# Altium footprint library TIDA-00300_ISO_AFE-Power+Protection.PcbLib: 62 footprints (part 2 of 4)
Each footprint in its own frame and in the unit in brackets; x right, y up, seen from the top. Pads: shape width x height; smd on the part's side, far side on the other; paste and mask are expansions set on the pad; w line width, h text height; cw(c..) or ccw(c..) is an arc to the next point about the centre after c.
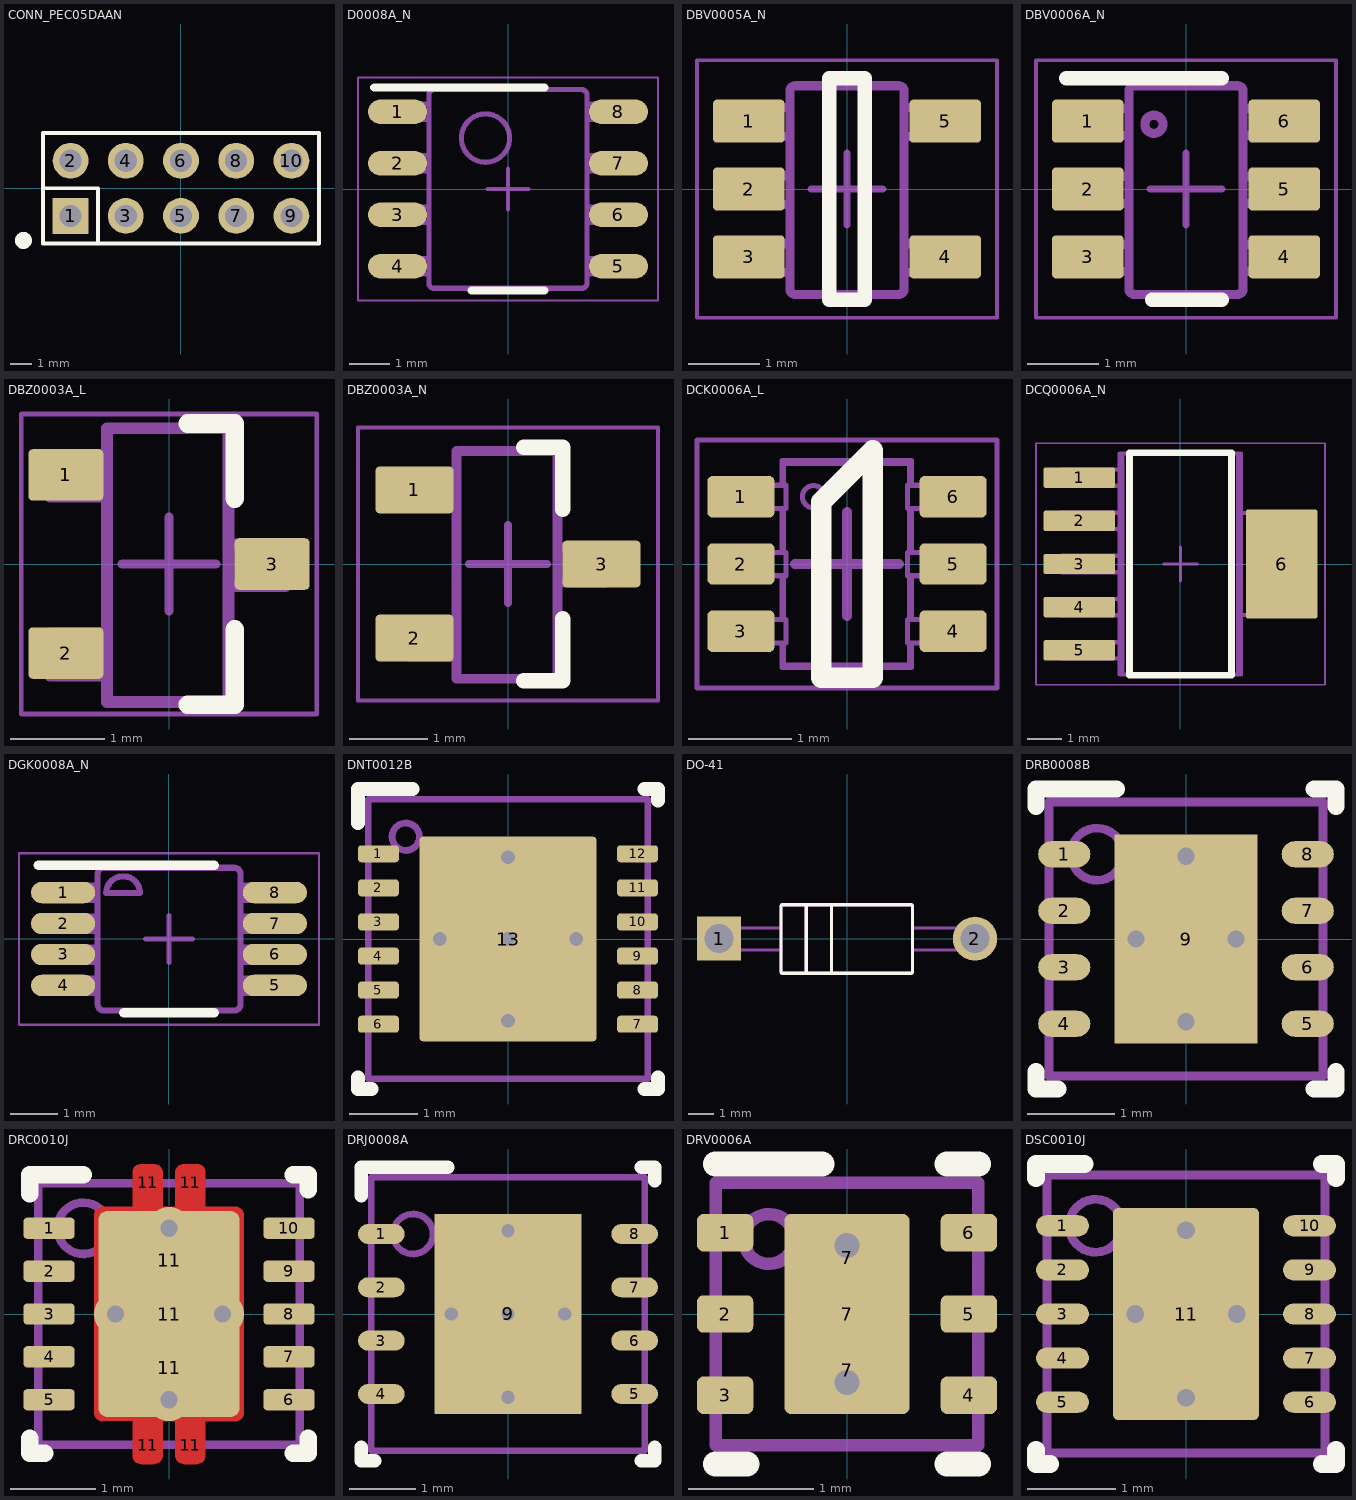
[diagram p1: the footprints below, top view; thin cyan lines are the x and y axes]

## CONN_PEC05DAAN [mm] "SULLINS"
height 8.382
pads (10):
  rect 1.65x1.65 hole 1.016 mask+0: 1(-5.08,-1.27)
  round 1.65 hole 1.016 mask+0: 2(-5.08,1.27) 3(-2.54,-1.27) 4(-2.54,1.27) 5(0,-1.27) 6(0,1.27) 7(2.54,-1.27) 8(2.54,1.27) 9(5.08,-1.27) 10(5.08,1.27)
Top Overlay:
  circle w0.381: c-7.25,-2.4 r0.203
  lines w0.178: -6.35,0 -3.81,0 -3.81,-2.54 ; -6.35,-2.54 -6.35,2.54 6.35,2.54 6.35,-2.54 -6.35,-2.54
Mechanical 5:
  rectangle: -5.588,-1.778 -4.572,-0.762
  lines w0.076: -6.35,-2.54 -6.35,2.54 6.35,2.54 6.35,-2.54 -6.35,-2.54
  lines w0.127: -6.35,-2.54 6.35,-2.54 6.35,2.54 -6.35,2.54 -6.35,-2.54
  text ".Designator" at -0.225,-0.532 h0.51
3D body: height 2.54, standoff 0, extent -6.349,-2.539 6.349,2.539
3D body: height 8.38, standoff -3.05, extent 4.763,0.953 5.398,1.588
3D body: height 8.38, standoff -3.05, extent 4.763,-1.587 5.398,-0.952
3D body: height 8.38, standoff -3.05, extent 2.223,0.953 2.858,1.588
3D body: height 8.38, standoff -3.05, extent 2.223,-1.587 2.858,-0.952
3D body: height 8.38, standoff -3.05, extent -0.317,0.953 0.318,1.588
3D body: height 8.38, standoff -3.05, extent -0.317,-1.587 0.318,-0.952
3D body: height 8.38, standoff -3.05, extent -2.857,-1.587 -2.222,-0.952
3D body: height 8.38, standoff -3.05, extent -2.857,0.953 -2.222,1.588
3D body: height 8.38, standoff -3.05, extent -5.397,0.953 -4.762,1.588
3D body: height 8.38, standoff -3.05, extent -5.397,-1.587 -4.762,-0.952

## D0008A_N [mm] "SOIC, 8-Leads, Body 4.9x3.9mm, Pitch 1.27mm, IPC Medium Density"
height 1.75
pads (8):
  oval 1.45x0.6 smd: 1(-2.725,1.905) 2(-2.725,0.635) 3(-2.725,-0.635) 4(-2.725,-1.905) 5(2.725,-1.905) 6(2.725,-0.635) 7(2.725,0.635) 8(2.725,1.905)
Top Overlay:
  lines w0.2: -3.3,2.5 0.9,2.5 ; -0.9,-2.5 0.9,-2.5
Mechanical 5:
  lines w0.127: -2.375,-2.095 -1.995,-2.095 -1.952,-2.095 -1.952,-1.715 -1.995,-1.715 -2.375,-1.715 ; -2.375,-2.095 -2.589,-2.095 -3.002,-2.095 -3.002,-1.715 -2.589,-1.715 -2.375,-1.715 ; -2.375,-2.095 -2.375,-1.715 ; -2.375,-0.825 -1.995,-0.825 -1.952,-0.825 -1.952,-0.445 -1.995,-0.445 -2.375,-0.445 ; -2.375,-0.825 -2.589,-0.825 -3.002,-0.825 -3.002,-0.445 -2.589,-0.445 -2.375,-0.445 ; -2.375,-0.825 -2.375,-0.445 ; -2.375,0.445 -1.995,0.445 -1.952,0.445 -1.952,0.825 -1.995,0.825 -2.375,0.825 ; -2.375,0.445 -2.589,0.445 -3.002,0.445 -3.002,0.825 -2.589,0.825 -2.375,0.825 ; -2.375,0.445 -2.375,0.825 ; -2.375,1.715 -1.995,1.715 -1.952,1.715 -1.952,2.095 -1.995,2.095 -2.375,2.095 ; -2.375,1.715 -2.589,1.715 -3.002,1.715 -3.002,2.095 -2.589,2.095 -2.375,2.095 ; -2.375,1.715 -2.375,2.095 ; -0.332,-2.45 -1.825,-2.45 -1.826,-2.45 cw(c-1.825,-2.323) -1.952,-2.324 -1.952,-2.323 -1.952,2.323 -1.952,2.324 cw(c-1.825,2.323) -1.826,2.45 -1.825,2.45 -0.332,2.45 ; -0.332,-2.45 -0.182,-2.45 ; -0.332,-2.45 -0.182,-2.45 ; -0.332,2.45 -0.182,2.45 ; -0.332,2.45 -0.182,2.45 ; -0.182,-2.45 0.178,-2.45 ; -0.182,2.45 0.178,2.45 ; 0.178,-2.45 0.328,-2.45 ; 0.178,-2.45 0.328,-2.45 ; 0.178,2.45 0.328,2.45 ; 0.178,2.45 0.328,2.45 ; 0.328,-2.45 1.821,-2.45 1.822,-2.45 ccw(c1.821,-2.323) 1.948,-2.324 1.948,-2.323 1.948,2.323 1.948,2.324 ccw(c1.821,2.323) 1.822,2.45 1.821,2.45 0.328,2.45 ; 2.371,-2.095 2.585,-2.095 2.998,-2.095 2.998,-1.715 2.585,-1.715 2.371,-1.715 ; 2.371,-2.095 1.991,-2.095 1.948,-2.095 1.948,-1.715 1.991,-1.715 2.371,-1.715 ; 2.371,-2.095 2.371,-1.715 ; 2.371,-0.825 2.585,-0.825 2.998,-0.825 2.998,-0.445 2.585,-0.445 2.371,-0.445 ; 2.371,-0.825 1.991,-0.825 1.948,-0.825 1.948,-0.445 1.991,-0.445 2.371,-0.445 ; 2.371,-0.825 2.371,-0.445 ; 2.371,0.445 2.585,0.445 2.998,0.445 2.998,0.825 2.585,0.825 2.371,0.825 ; 2.371,0.445 1.991,0.445 1.948,0.445 1.948,0.825 1.991,0.825 2.371,0.825 ; 2.371,0.445 2.371,0.825 ; 2.371,1.715 2.585,1.715 2.998,1.715 2.998,2.095 2.585,2.095 2.371,2.095 ; 2.371,1.715 1.991,1.715 1.948,1.715 1.948,2.095 1.991,2.095 2.371,2.095 ; 2.371,1.715 2.371,2.095 ; -0.555,0.659 cw(c-0.555,1.256) -0.555,1.853 cw(c-0.555,1.256) -0.555,0.659
  text ".Designator" at 0.605,-0.197 h0.51
Mechanical 15:
  lines w0.05: -3.7,-2.75 3.7,-2.75 3.7,2.75 -3.7,2.75 -3.7,-2.75
  lines w0.1: -0.5,0 0.5,0 ; 0,-0.5 0,0.5
3D body "D0008A.stp": height 1.63, standoff 0, extent -3,-2.45 3,2.45

## DBV0005A_N [mm] "SOT23, 5-Leads, Body 2.9x1.6mm, Pitch 0.95mm, Lead Span 2.8mm, IPC Medium Density"
height 1.45
pads (5):
  rrect17% 1x0.6 smd: 1(-1.375,0.95) 2(-1.375,0) 3(-1.375,-0.95) 4(1.375,-0.95) 5(1.375,0.95)
Top Overlay:
  lines w0.2: -0.25,-1.55 -0.25,1.55 0.25,1.55 0.25,-1.55 -0.25,-1.55
Mechanical 5:
  lines w0.127: -0.801,1.371 cw(c-0.725,1.37) -0.725,1.446 ; -0.801,1.37 -0.801,1.371 ; -0.801,1.37 -0.801,-1.399 -0.801,-1.4 ccw(c-0.725,-1.399) -0.725,-1.475 ; -0.725,-1.475 0.723,-1.475 0.724,-1.475 ccw(c0.723,-1.399) 0.799,-1.4 0.799,-1.399 0.799,1.37 ; -0.725,-1.475 -0.725,-1.475 ; -0.725,1.446 -0.725,1.446 ; -0.725,1.446 0.723,1.446 0.724,1.446 cw(c0.723,1.37) 0.799,1.371 ; 0.799,1.37 0.799,1.371 ; -1.423,-1.167 -1.423,-0.767 -1.199,-0.767 -1.105,-0.767 -1.088,-0.767 -0.835,-0.767 -0.801,-0.767 -0.801,-1.167 -0.835,-1.167 -1.088,-1.167 -1.105,-1.167 -1.199,-1.167 -1.423,-1.167 ; -1.423,-0.215 -1.423,0.186 -1.199,0.186 -1.105,0.186 -1.088,0.186 -0.835,0.186 -0.801,0.186 -0.801,-0.215 -0.835,-0.215 -1.088,-0.215 -1.105,-0.215 -1.199,-0.215 -1.423,-0.215 ; -1.423,0.738 -1.423,1.138 -1.199,1.138 -1.105,1.138 -1.088,1.138 -0.835,1.138 -0.801,1.138 -0.801,0.738 -0.835,0.738 -1.088,0.738 -1.105,0.738 -1.199,0.738 -1.423,0.738 ; 0.799,-1.167 0.834,-1.167 1.087,-1.167 1.103,-1.167 1.198,-1.167 1.422,-1.167 1.422,-0.767 1.198,-0.767 1.103,-0.767 1.087,-0.767 0.834,-0.767 0.799,-0.767 0.799,-1.167 ; 0.799,0.738 0.834,0.738 1.087,0.738 1.103,0.738 1.198,0.738 1.422,0.738 1.422,1.138 1.198,1.138 1.103,1.138 1.087,1.138 0.834,1.138 0.799,1.138 0.799,0.738
  text ".Designator" at 0.25,-1.081 h0.51
Mechanical 15:
  lines w0.05: -2.1,-1.8 -2.1,1.8 2.1,1.8 2.1,-1.8 -2.1,-1.8
  lines w0.1: -0.5,0 0.5,0 ; 0,-0.5 0,0.5
3D body "DBV0005A.stp": height 1.09, standoff 0, extent -1.422,-1.461 1.423,1.46

## DBV0006A_N [mm] "SOT23, 6-Leads, Body 2.9x1.6mm, Pitch 0.95mm, Lead Span 2.8mm, IPC Medium Density"
height 1.45
pads (6):
  rrect17% 1x0.6 smd: 1(-1.375,0.95) 2(-1.375,0) 3(-1.375,-0.95) 4(1.375,-0.95) 5(1.375,0) 6(1.375,0.95)
Top Overlay:
  lines w0.2: -1.675,1.55 0.5,1.55 ; -0.475,-1.55 0.5,-1.55
Mechanical 5:
  lines w0.127: 0.724,-1.475 ccw(c0.723,-1.399) 0.8,-1.399 0.8,1.37 ccw(c0.723,1.37) 0.724,1.446 ; 0.723,-1.475 -0.724,-1.475 -0.725,-1.475 cw(c-0.724,-1.399) -0.801,-1.399 -0.801,1.37 cw(c-0.724,1.37) -0.725,1.446 -0.724,1.446 0.723,1.446 ; 0.723,-1.475 0.724,-1.475 ; 0.723,1.446 0.724,1.446 ; -1.423,-1.154 -1.423,-0.78 -1.206,-0.78 -1.113,-0.78 -1.081,-0.78 -0.828,-0.78 -0.801,-0.78 -0.801,-1.154 -0.828,-1.154 -1.081,-1.154 -1.113,-1.154 -1.206,-1.154 -1.423,-1.154 ; -1.423,-0.202 -1.423,0.173 -1.206,0.173 -1.113,0.173 -1.081,0.173 -0.828,0.173 -0.801,0.173 -0.801,-0.202 -0.828,-0.202 -1.081,-0.202 -1.113,-0.202 -1.206,-0.202 -1.423,-0.202 ; -1.423,0.751 -1.423,1.125 -1.206,1.125 -1.113,1.125 -1.081,1.125 -0.828,1.125 -0.801,1.125 -0.801,0.751 -0.828,0.751 -1.081,0.751 -1.113,0.751 -1.206,0.751 -1.423,0.751 ; -0.577,0.906 ccw(c-0.45,0.906) -0.323,0.906 ccw(c-0.45,0.906) -0.577,0.906 ; 0.8,-1.154 0.8,-0.78 0.827,-0.78 1.08,-0.78 1.112,-0.78 1.205,-0.78 1.422,-0.78 1.422,-1.154 1.205,-1.154 1.112,-1.154 1.08,-1.154 0.827,-1.154 0.8,-1.154 ; 0.8,-0.202 0.8,0.173 0.827,0.173 1.08,0.173 1.112,0.173 1.205,0.173 1.422,0.173 1.422,-0.202 1.205,-0.202 1.112,-0.202 1.08,-0.202 0.827,-0.202 0.8,-0.202 ; 0.8,0.751 0.8,1.125 0.827,1.125 1.08,1.125 1.112,1.125 1.205,1.125 1.422,1.125 1.422,0.751 1.205,0.751 1.112,0.751 1.08,0.751 0.827,0.751 0.8,0.751
  text ".Designator" at -0.207,0.323 h0.51
Mechanical 15:
  lines w0.05: -2.1,-1.8 -2.1,1.8 2.1,1.8 2.1,-1.8 -2.1,-1.8
  lines w0.1: -0.5,0 0.5,0 ; 0,-0.5 0,0.5
3D body "DBV0006A.stp": height 1.12, standoff 0, extent -1.422,-1.461 1.423,1.46

## DBZ0003A_L [mm] "SOT23, 3-Leads, Body 2.9x1.3mm, Pitch 0.95mm, Lead Span 2.4mm, IPC High Density"
height 1.12
pads (3):
  rrect18% 0.8x0.55 smd: 1(-1.1,0.95) 2(-1.1,-0.95) 3(1.1,0)
Top Overlay:
  lines w0.2: 0.2,-1.5 0.7,-1.5 0.7,-0.7 ; 0.2,1.5 0.7,1.5 0.7,0.7
Mechanical 5:
  lines w0.127: -1.27,-1.187 -1.063,-1.187 -1.005,-1.187 -0.814,-1.187 -0.66,-1.187 -0.66,-0.743 -0.814,-0.743 -1.005,-0.743 -1.063,-0.743 -1.27,-0.743 -1.27,-1.187 ; -1.27,0.718 -1.063,0.718 -1.005,0.718 -0.814,0.718 -0.66,0.718 -0.66,1.162 -0.814,1.162 -1.005,1.162 -1.063,1.162 -1.27,1.162 -1.27,0.718 ; -0.66,-1.473 0.635,-1.473 0.635,1.448 -0.66,1.448 -0.66,-1.473 ; 0.635,-0.235 0.635,0.21 0.789,0.21 0.98,0.21 1.037,0.21 1.245,0.21 1.245,-0.235 1.037,-0.235 0.98,-0.235 0.789,-0.235 0.635,-0.235
  text ".Designator" at 0.186,-1.108 h0.51
Mechanical 15:
  lines w0.05: -1.575,-1.6 1.575,-1.6 1.575,1.6 -1.575,1.6 -1.575,-1.6
  lines w0.1: -0.5,0 0.5,0 ; 0,-0.5 0,0.5
3D body "DBZ0003A.stp": height 0.98, standoff 0, extent -1.257,-1.461 1.258,1.461

## DBZ0003A_N [mm] "SOT23, 3-Leads, Body 2.9x1.3mm, Pitch 0.95mm, Lead Span 2.4mm, IPC Medium Density"
height 1.12
pads (3):
  rrect17% 1x0.6 smd: 1(-1.2,0.95) 2(-1.2,-0.95) 3(1.2,0)
Top Overlay:
  lines w0.2: 0.2,-1.5 0.7,-1.5 0.7,-0.7 ; 0.2,1.5 0.7,1.5 0.7,0.7
Mechanical 5:
  lines w0.127: -1.27,-1.187 -1.27,-0.743 -1.063,-0.743 -1.005,-0.743 -0.814,-0.743 -0.66,-0.743 -0.66,-1.187 -0.814,-1.187 -1.005,-1.187 -1.063,-1.187 -1.27,-1.187 ; -1.27,0.718 -1.27,1.162 -1.063,1.162 -1.005,1.162 -0.814,1.162 -0.66,1.162 -0.66,0.718 -0.814,0.718 -1.005,0.718 -1.063,0.718 -1.27,0.718 ; -0.66,-1.473 -0.66,1.448 0.635,1.448 0.635,-1.473 -0.66,-1.473 ; 0.635,-0.235 0.789,-0.235 0.98,-0.235 1.037,-0.235 1.245,-0.235 1.245,0.21 1.037,0.21 0.98,0.21 0.789,0.21 0.635,0.21 0.635,-0.235
  text ".Designator" at -0.203,0.051 h0.51
Mechanical 15:
  lines w0.05: -1.925,-1.75 1.925,-1.75 1.925,1.75 -1.925,1.75 -1.925,-1.75
  lines w0.1: -0.5,0 0.5,0 ; 0,-0.5 0,0.5
3D body "DBZ0003A.stp": height 0.98, standoff 0, extent -1.257,-1.461 1.258,1.461

## DCK0006A_L [mm] "SOT23, 6-Leads, Body 2x1.3mm, Pitch 0.65mm, Lead Span 2.1mm, IPC High Density"
height 1.1
pads (6):
  rrect25% 0.65x0.4 smd: 1(-1.025,0.65) 2(-1.025,0) 3(-1.025,-0.65) 4(1.025,-0.65) 5(1.025,0) 6(1.025,0.65)
Top Overlay:
  lines w0.2: -0.25,-1.1 -0.25,0.6 0.25,1.1 0.25,-1.1 -0.25,-1.1
Mechanical 5:
  lines w0.05: -0.613,-0.763 -0.613,-0.976 0.607,-0.976 0.607,-0.763 ; -0.613,-0.538 -0.613,-0.113 ; -0.613,0.112 -0.613,0.537 ; -0.613,0.762 -0.613,0.974 0.607,0.974 0.607,0.762 ; 0.607,-0.538 0.607,-0.113 ; 0.607,0.112 0.607,0.537 ; -0.628,-0.763 -0.628,-1.001 0.622,-1.001 0.622,-0.763 ; -0.628,-0.763 -0.853,-0.763 -0.865,-0.763 -0.959,-0.763 -1.143,-0.763 -1.143,-0.538 -0.959,-0.538 -0.865,-0.538 -0.853,-0.538 -0.628,-0.538 ; -0.628,-0.763 -0.591,-0.763 -0.591,-0.538 -0.628,-0.538 ; -0.628,-0.538 -0.628,-0.113 ; -0.628,-0.113 -0.853,-0.113 -0.865,-0.113 -0.959,-0.113 -1.143,-0.113 -1.143,0.112 -0.959,0.112 -0.865,0.112 -0.853,0.112 -0.628,0.112 ; -0.628,-0.113 -0.591,-0.113 -0.591,0.112 -0.628,0.112 ; -0.628,0.112 -0.628,0.537 ; -0.628,0.537 -0.853,0.537 -0.865,0.537 -0.959,0.537 -1.143,0.537 -1.143,0.762 -0.959,0.762 -0.865,0.762 -0.853,0.762 -0.628,0.762 ; -0.628,0.537 -0.591,0.537 -0.591,0.762 -0.628,0.762 ; -0.628,0.762 -0.628,0.999 0.622,0.999 0.622,0.762 ; 0.622,-0.763 0.847,-0.763 0.859,-0.763 0.953,-0.763 1.137,-0.763 1.137,-0.538 0.953,-0.538 0.859,-0.538 0.847,-0.538 0.622,-0.538 ; 0.622,-0.763 0.585,-0.763 0.585,-0.538 0.622,-0.538 ; 0.622,-0.538 0.622,-0.113 ; 0.622,-0.113 0.585,-0.113 0.585,0.112 0.622,0.112 ; 0.622,-0.113 0.847,-0.113 0.859,-0.113 0.953,-0.113 1.137,-0.113 1.137,0.112 0.953,0.112 0.859,0.112 0.847,0.112 0.622,0.112 ; 0.622,0.112 0.622,0.537 ; 0.622,0.537 0.847,0.537 0.859,0.537 0.953,0.537 1.137,0.537 1.137,0.762 0.953,0.762 0.859,0.762 0.847,0.762 0.622,0.762 ; 0.622,0.537 0.585,0.537 0.585,0.762 0.622,0.762 ; -0.432,0.65 cw(c-0.323,0.65) -0.215,0.65 cw(c-0.323,0.65) -0.432,0.65
  text ".Designator" at -0.051,0.66 h0.51
Mechanical 15:
  lines w0.05: -1.45,-1.2 1.45,-1.2 1.45,1.2 -1.45,1.2 -1.45,-1.2
  lines w0.1: -0.5,0 0.5,0 ; 0,-0.5 0,0.5
3D body "DCK0006A.stp": height 0.95, standoff 0, extent -1.14,-1 1.14,1

## DCQ0006A_N [mm] "SOT223, 6-Leads, Body 6.6x7.3mm (max), Pitch 1.27mm, IPC Medium Density"
height 1.8
pads (6):
  rrect17% 2.1x0.6 smd: 1(-2.975,2.54) 2(-2.975,1.27) 3(-2.975,0) 4(-2.975,-1.27) 5(-2.975,-2.54)
  rrect5% 2.1x3.2 smd: 6(2.975,0)
Top Overlay:
  lines w0.2: -1.5,-3.275 1.5,-3.275 1.5,3.275 -1.5,3.275 -1.5,-3.275
Mechanical 5:
  lines w0.127: -1.713,-3.178 -1.785,-3.25 ; -1.713,3.178 -1.785,3.25 ; -1.707,-3.102 -1.707,3.102 ; 1.697,-3.102 1.697,3.102 ; 1.703,-3.178 1.775,-3.25 ; 1.703,3.178 1.775,3.25 ; -1.785,-3.25 1.775,-3.25 ; -1.785,-3.25 -1.785,3.25 ; -1.785,3.25 1.775,3.25 ; 1.775,-3.25 1.775,3.25 ; -3.485,-2.781 -3.485,-2.299 -2.951,-2.299 -2.834,-2.299 -2.758,-2.299 -2.364,-2.299 -1.785,-2.299 -1.785,-2.781 -2.364,-2.781 -2.758,-2.781 -2.834,-2.781 -2.951,-2.781 -3.485,-2.781 ; -3.485,-1.511 -3.485,-1.029 -2.951,-1.029 -2.834,-1.029 -2.758,-1.029 -2.364,-1.029 -1.785,-1.029 -1.785,-1.511 -2.364,-1.511 -2.758,-1.511 -2.834,-1.511 -2.951,-1.511 -3.485,-1.511 ; -3.485,-0.241 -3.485,0.241 -2.951,0.241 -2.834,0.241 -2.758,0.241 -2.364,0.241 -1.785,0.241 -1.785,-0.241 -2.364,-0.241 -2.758,-0.241 -2.834,-0.241 -2.951,-0.241 -3.485,-0.241 ; -3.485,1.029 -3.485,1.511 -2.951,1.511 -2.834,1.511 -2.758,1.511 -2.364,1.511 -1.785,1.511 -1.785,1.029 -2.364,1.029 -2.758,1.029 -2.834,1.029 -2.951,1.029 -3.485,1.029 ; -3.485,2.299 -3.485,2.781 -2.951,2.781 -2.834,2.781 -2.758,2.781 -2.364,2.781 -1.785,2.781 -1.785,2.299 -2.364,2.299 -2.758,2.299 -2.834,2.299 -2.951,2.299 -3.485,2.299 ; 1.775,-1.5 1.775,1.5 2.354,1.5 2.748,1.5 2.824,1.5 2.941,1.5 3.475,1.5 3.475,-1.5 2.941,-1.5 2.824,-1.5 2.748,-1.5 2.354,-1.5 1.775,-1.5
  text ".Designator" at 0.277,-0.725 h0.51
Mechanical 15:
  lines w0.05: -4.25,-3.55 -4.25,3.55 4.25,3.55 4.25,-3.55 -4.25,-3.55
  lines w0.1: -0.5,0 0.5,0 ; 0,-0.5 0,0.5
3D body "DCQ0006A.stp": height 1.8, standoff 0, extent -3.542,-3.25 3.542,3.25

## DGK0008A_N [mm] "TSOP, 8-Leads, Body 3x3mm, Pitch 0.65mm, IPC Medium Density"
height 1.1
pads (8):
  oval 1.35x0.45 smd: 1(-2.225,0.975) 2(-2.225,0.325) 3(-2.225,-0.325) 4(-2.225,-0.975) 5(2.225,-0.975) 6(2.225,-0.325) 7(2.225,0.325) 8(2.225,0.975)
Top Overlay:
  lines w0.2: -2.75,1.55 0.95,1.55 ; -0.95,-1.55 0.95,-1.55
Mechanical 5:
  lines w0.127: -2.45,-1.131 -2.21,-1.131 -2.091,-1.131 -2.087,-1.131 -1.784,-1.131 -1.498,-1.131 -1.498,-0.826 -1.784,-0.826 -2.087,-0.826 -2.091,-0.826 -2.21,-0.826 -2.45,-0.826 -2.45,-1.131 ; -2.45,-0.48 -2.21,-0.48 -2.091,-0.48 -2.087,-0.48 -1.784,-0.48 -1.498,-0.48 -1.498,-0.175 -1.784,-0.175 -2.087,-0.175 -2.091,-0.175 -2.21,-0.175 -2.45,-0.175 -2.45,-0.48 ; -2.45,0.17 -2.21,0.17 -2.091,0.17 -2.087,0.17 -1.784,0.17 -1.498,0.17 -1.498,0.475 -1.784,0.475 -2.087,0.475 -2.091,0.475 -2.21,0.475 -2.45,0.475 -2.45,0.17 ; -2.45,0.82 -2.21,0.82 -2.091,0.82 -2.087,0.82 -1.784,0.82 -1.498,0.82 -1.498,1.125 -1.784,1.125 -2.087,1.125 -2.091,1.125 -2.21,1.125 -2.45,1.125 -2.45,0.82 ; -1.497,-1.377 ccw(c-1.37,-1.374) -1.373,-1.501 -1.371,-1.501 1.373,-1.501 1.375,-1.501 ccw(c1.373,-1.374) 1.5,-1.377 1.5,-1.374 1.5,1.369 1.5,1.372 ccw(c1.373,1.369) 1.375,1.496 1.373,1.496 -1.371,1.496 -1.373,1.496 ccw(c-1.37,1.369) -1.497,1.372 -1.498,1.369 -1.498,-1.374 -1.497,-1.377 ; -1.32,0.962 cw(c-0.964,0.962) -0.609,0.962 -1.32,0.962 ; 1.5,-1.131 1.5,-0.826 1.786,-0.826 2.089,-0.826 2.093,-0.826 2.213,-0.826 2.452,-0.826 2.452,-1.131 2.213,-1.131 2.093,-1.131 2.089,-1.131 1.786,-1.131 1.5,-1.131 ; 1.5,-0.48 1.5,-0.175 1.786,-0.175 2.089,-0.175 2.093,-0.175 2.213,-0.175 2.452,-0.175 2.452,-0.48 2.213,-0.48 2.093,-0.48 2.089,-0.48 1.786,-0.48 1.5,-0.48 ; 1.5,0.17 1.5,0.475 1.786,0.475 2.089,0.475 2.093,0.475 2.213,0.475 2.452,0.475 2.452,0.17 2.213,0.17 2.093,0.17 2.089,0.17 1.786,0.17 1.5,0.17 ; 1.5,0.82 1.5,1.125 1.786,1.125 2.089,1.125 2.093,1.125 2.213,1.125 2.452,1.125 2.452,0.82 2.213,0.82 2.093,0.82 2.089,0.82 1.786,0.82 1.5,0.82
  text ".Designator" at -1.15,-0.3 h0.51
Mechanical 15:
  lines w0.05: -3.15,-1.8 3.15,-1.8 3.15,1.8 -3.15,1.8 -3.15,-1.8
  lines w0.1: -0.5,0 0.5,0 ; 0,-0.5 0,0.5
3D body "DGK0008A.stp": height 0.96, standoff 0, extent -2.451,-1.499 2.451,1.499

## DNT0012B [mm] "SON, 12-Leads, Body 4x4mm, Pitch 0.5mm"
height 0.8
pads (13):
  rrect40% 0.6x0.25 smd: 1(-1.9,1.25) 2(-1.9,0.75) 3(-1.9,0.25) 4(-1.9,-0.25) 5(-1.9,-0.75) 6(-1.9,-1.25) 7(1.9,-1.25) 8(1.9,-0.75) 9(1.9,-0.25) 10(1.9,0.25) 11(1.9,0.75) 12(1.9,1.25)
  rrect4% 2.6x3 smd paste-1.3: 13(0,0)
via 0,1.2 diameter 0.5 hole 0.2
via 1,0 diameter 0.5 hole 0.2
via 0,0 diameter 0.5 hole 0.2
via 0,-1.2 diameter 0.5 hole 0.2
via -1,0 diameter 0.5 hole 0.2
Top Overlay:
  lines w0.2: -2.2,-2.025 -2.2,-2.2 -2,-2.2 ; -2.2,1.7 -2.2,2.2 -1.4,2.2 ; 2,-2.2 2.2,-2.2 2.2,-2.025 ; 2,2.2 2.2,2.2 2.2,2.025
Top Paste:
  rectangle: 0.1,0.1 1.248,1.41
  region: -0.1,1.41 -1.248,1.41 -1.248,0.1 -0.1,0.1
  rectangle: 0.1,-1.41 1.248,-0.1
  region: -0.1,-0.1 -1.248,-0.1 -1.248,-1.41 -0.1,-1.41
Mechanical 5:
  circle w0.1: c-1.5,1.5 r0.2
  lines w0.1: -2.05,-2.05 2.05,-2.05 2.05,2.05 -2.05,2.05 -2.05,-2.05
  text ".Designator" at -0.047,-0.145 h0.51
3D body: height 0.8, standoff 0, extent -2.049,-2.049 2.049,2.049
3D body: height 0.81, standoff 0.5, extent -1.699,1.301 -1.301,1.699

## DO-41 [mm] "diode"
height 3
pads (2):
  rect 1.75x1.75 hole 1.15: 1(-5.08,0)
  round 1.75 hole 1.15: 2(5.08,0)
Top Overlay:
  lines w0.127: -1.615,-1.371 -0.615,-1.371 ; -1.615,1.347 -0.615,1.347 ; -2.615,-1.322 ccw(c-2.565,-1.322) -2.565,-1.372 -1.615,-1.372 -1.615,-0.012 -1.615,1.348 -2.565,1.348 ccw(c-2.565,1.298) -2.615,1.298 -2.615,-0.012 -2.615,-1.322 ; -0.615,-1.372 2.545,-1.372 ccw(c2.545,-1.322) 2.595,-1.322 2.595,1.298 ccw(c2.545,1.298) 2.545,1.348 -0.615,1.348 -0.615,-1.372
Mechanical 5:
  lines w0.127: -2.615,-0.444 -4.09,-0.444 -5.09,-0.444 cw(c-5.09,-0.012) -5.522,-0.012 cw(c-5.09,-0.012) -5.09,0.42 -4.09,0.42 -2.615,0.42 ; -1.615,-1.371 -0.615,-1.371 ; -1.615,1.347 -0.615,1.347 ; 2.595,-0.444 4.07,-0.444 5.07,-0.444 ccw(c5.07,-0.012) 5.502,-0.012 ccw(c5.07,-0.012) 5.07,0.42 4.07,0.42 2.595,0.42 ; -2.615,-1.322 ccw(c-2.565,-1.322) -2.565,-1.372 -1.615,-1.372 -1.615,-0.012 -1.615,1.348 -2.565,1.348 ccw(c-2.565,1.298) -2.615,1.298 -2.615,-0.012 -2.615,-1.322 ; -0.615,-1.372 -0.615,1.348 2.545,1.348 cw(c2.545,1.298) 2.595,1.298 2.595,-1.322 cw(c2.545,-1.322) 2.545,-1.372 -0.615,-1.372
  text ".Designator" at 0.315,-0.175 h0.51
3D body "DO-41.stp": height 2.72, standoff -2.6, extent -5.512,-1.36 5.512,1.36

## DRB0008B [mm] "SON, 8-Leads, Body 3x3mm, Pitch 0.65mm, Thermal Pad 2.4x1.65mm, TI Recommended"
height 1
pads (9):
  oval 0.6x0.3 smd: 1(-1.4,0.975) 2(-1.4,0.325) 3(-1.4,-0.325) 4(-1.4,-0.975) 5(1.4,-0.975) 6(1.4,-0.325) 7(1.4,0.325) 8(1.4,0.975)
  rect 1.65x2.4 smd paste-1.2: 9(0,0)
via 0,-0.95 diameter 0.5 hole 0.2
via 0,0.95 diameter 0.5 hole 0.2
via 0.575,0 diameter 0.5 hole 0.2
via -0.575,0 diameter 0.5 hole 0.2
Top Overlay:
  lines w0.2: -1.725,-1.525 -1.725,-1.725 -1.475,-1.725 ; -1.725,1.525 -1.725,1.725 -0.8,1.725 ; 1.475,-1.725 1.725,-1.725 1.725,-1.525 ; 1.475,1.725 1.725,1.725 1.725,1.525
Top Paste:
  rectangle: -0.752,-1.143 0.751,-0.1
  rectangle: -0.752,0.1 0.751,1.143
Mechanical 5:
  circle w0.1: c-1.025,0.975 r0.3
  lines w0.1: -1.575,-1.575 -1.575,1.575 1.575,1.575 1.575,-1.575 -1.575,-1.575
  text ".Designator" at -0.062,0.781 h0.51
3D body: height 1, standoff 0, extent -1.575,-1.575 1.575,1.575
3D body: height 1.01, standoff 0.5, extent -1.324,0.676 -0.726,1.274

## DRC0010J [mm] "SON, 10-Leads, Body 3x3mm, Pitch 0.5mm, Thermal Pad 2.4x1.65mm, TI Recommended"
height 1
pads (17):
  rrect40% 0.6x0.25 smd: 1(-1.4,1) 2(-1.4,0.5) 3(-1.4,0) 4(-1.4,-0.5) 5(-1.4,-1) 6(1.4,-1) 7(1.4,-0.5) 8(1.4,0) 9(1.4,0.5) 10(1.4,1)
  rrect50% 0.25x0.34 on Top Paste: 11(-0.25,-1.53) 11(-0.25,1.53) 11(0.25,-1.53) 11(0.25,1.53)
  rrect50% 1.5x1.06 on Top Paste: 11(0,-0.63) 11(0,0.63)
  rrect12% 1.65x2.4 smd paste-1 mask-2: 11(0,0)
via 0,-1 diameter 0.5 hole 0.2
via 0,1 diameter 0.5 hole 0.2
via -0.625,0 diameter 0.5 hole 0.2
via 0.625,0 diameter 0.5 hole 0.2
Top Layer:
  region: -0.775,-1.25 -0.425,-1.25 -0.425,-1.65 -0.425,-1.67 -0.41,-1.707 -0.382,-1.735 -0.345,-1.75 -0.325,-1.75 -0.175,-1.75 -0.155,-1.75 -0.118,-1.735 -0.09,-1.707 -0.075,-1.67 -0.075,-1.65 -0.075,-1.25 0.075,-1.25 0.075,-1.65 0.075,-1.67 0.09,-1.707 0.118,-1.735 0.155,-1.75 0.175,-1.75 0.325,-1.75 0.345,-1.75 0.382,-1.735 0.41,-1.707 0.425,-1.67 0.425,-1.65 0.425,-1.25 0.775,-1.25 0.795,-1.25 0.832,-1.235 0.86,-1.207 0.875,-1.17 0.875,-1.15 0.875,1.15 0.875,1.17 0.86,1.207 0.832,1.235 0.795,1.25 0.775,1.25 0.425,1.25 0.425,1.65 0.425,1.67 0.41,1.707 0.382,1.735 0.345,1.75 0.325,1.75 0.175,1.75 0.155,1.75 0.118,1.735 0.09,1.707 0.075,1.67 0.075,1.65 0.075,1.25 -0.075,1.25 -0.075,1.65 -0.075,1.67 -0.09,1.707 -0.118,1.735 -0.155,1.75 -0.175,1.75 -0.325,1.75 -0.345,1.75 -0.382,1.735 -0.41,1.707 -0.425,1.67 -0.425,1.65 -0.425,1.25 -0.775,1.25 -0.795,1.25 -0.832,1.235 -0.86,1.207 -0.875,1.17 -0.875,1.15 -0.875,-1.15 -0.875,-1.17 -0.86,-1.207 -0.832,-1.235 -0.795,-1.25
Top Overlay:
  lines w0.2: -1.625,-1.45 -1.625,-1.625 -1.45,-1.625 ; -1.625,1.4 -1.625,1.625 -1,1.625 ; 1.45,-1.625 1.625,-1.625 1.625,-1.45 ; 1.45,1.625 1.625,1.625 1.625,1.45
Mechanical 5:
  circle w0.1: c-1,1 r0.3
  lines w0.1: -1.525,-1.525 1.525,-1.525 1.525,1.525 -1.525,1.525 -1.525,-1.525
  text ".Designator" at -3.831,-0.863 h0.51
3D body "DRC0010J.stp": height 0.77, standoff 0, extent -1.5,-1.5 1.5,1.5

## DRJ0008A [mm] "SON, 8-Leads, Body 4x4mm, Pitch 0.8mm, Thermal Pad 3x2.2mm, TI Recommended"
height 0.8
pads (9):
  oval 0.7x0.3 smd: 1(-1.9,1.2) 2(-1.9,0.4) 3(-1.9,-0.4) 4(-1.9,-1.2) 5(1.9,-1.2) 6(1.9,-0.4) 7(1.9,0.4) 8(1.9,1.2)
  rect 2.2x3 smd paste-1.1: 9(0,0)
via -0.85,0 diameter 0.5 hole 0.2
via 0,-1.25 diameter 0.5 hole 0.2
via 0,1.25 diameter 0.5 hole 0.2
via 0,0 diameter 0.5 hole 0.2
via 0.85,0 diameter 0.5 hole 0.2
Top Overlay:
  lines w0.2: -2.2,-2 -2.2,-2.2 -2,-2.2 ; -2.2,1.775 -2.2,2.2 -0.9,2.2 ; 2,-2.2 2.2,-2.2 2.2,-2 ; 2,2.2 2.2,2.2 2.2,2
Top Paste:
  rectangle: 0.1,-1.41 1.081,-0.1
  region: -0.1,-0.1 -1.081,-0.1 -1.081,-1.41 -0.1,-1.41
  region: -0.1,1.41 -1.081,1.41 -1.081,0.1 -0.1,0.1
  rectangle: 0.1,0.1 1.081,1.41
Mechanical 5:
  circle w0.1: c-1.425,1.2 r0.3
  lines w0.1: -2.05,-2.05 -2.05,2.05 2.05,2.05 2.05,-2.05 -2.05,-2.05
  text ".Designator" at -0.041,0.714 h0.51
3D body: height 0.8, standoff 0, extent -2.05,-2.05 2.05,2.05
3D body: height 0.81, standoff 0.5, extent -1.724,0.901 -1.126,1.499

## DRV0006A [mm] "SON, 6-Leads, Body 2x2mm, Pitch 0.65mm, Thermal Pad 1.6x1mm, TI Recommended"
height 0.8
pads (9):
  rrect33% 0.45x0.3 smd: 1(-0.975,0.65) 2(-0.975,0) 3(-0.975,-0.65) 4(0.975,-0.65) 5(0.975,0) 6(0.975,0.65)
  rrect50% 1x0.7 on Top Paste: 7(0,-0.45) 7(0,0.45)
  rrect10% 1x1.6 smd paste-0.5: 7(0,0)
via 0,-0.55 diameter 0.5 hole 0.2
via 0,0.55 diameter 0.5 hole 0.2
Top Overlay:
  lines w0.2: -1.05,-1.2 -0.8,-1.2 ; -1.05,1.2 -0.2,1.2 ; 0.8,-1.2 1.05,-1.2 ; 0.8,1.2 1.05,1.2
Mechanical 5:
  circle w0.1: c-0.625,0.6 r0.2
  lines w0.1: -1.05,-1.05 1.05,-1.05 1.05,1.05 -1.05,1.05 -1.05,-1.05
  text ".Designator" at 0.806,0.044 h0.51
3D body: height 0.8, standoff 0, extent -1.05,-1.05 1.05,1.05
3D body: height 0.81, standoff 0.5, extent -0.824,0.401 -0.426,0.799

## DSC0010J [mm] "SON, 10-Leads, Body 3x3mm, Pitch 0.5mm, Thermal Pad 2.4x1.65mm, TI Recommended"
height 0.8
pads (11):
  rrect100% 0.6x0.24 smd: 1(-1.4,1) 2(-1.4,0.5) 3(-1.4,0) 4(-1.4,-0.5) 5(-1.4,-1) 6(1.4,-1) 7(1.4,-0.5) 8(1.4,0) 9(1.4,0.5) 10(1.4,1)
  rrect6% 1.65x2.4 smd paste-0.825: 11(0,0)
via 0.575,0 diameter 0.5 hole 0.2
via -0.575,0 diameter 0.5 hole 0.2
via 0,0.95 diameter 0.5 hole 0.2
via 0,-0.95 diameter 0.5 hole 0.2
Top Overlay:
  lines w0.2: -1.7,-1.54 -1.7,-1.7 -1.54,-1.7 ; -1.7,1.54 -1.7,1.7 -1.15,1.7 ; 1.54,-1.7 1.7,-1.7 1.7,-1.54 ; 1.54,1.7 1.7,1.7 1.7,1.54
Top Paste:
  rectangle: -0.75,0.1 0.75,1.16
  rectangle: -0.75,-1.16 0.75,-0.1
Mechanical 5:
  circle w0.1: c-1.025,1 r0.3
  lines w0.1: -1.575,-1.575 1.575,-1.575 1.575,1.575 -1.575,1.575 -1.575,-1.575
  text ".Designator" at 0.377,0.272 h0.51
3D body: height 0.8, standoff 0, extent -1.574,-1.574 1.574,1.574
3D body: height 0.81, standoff 0.5, extent -1.324,0.701 -0.726,1.299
